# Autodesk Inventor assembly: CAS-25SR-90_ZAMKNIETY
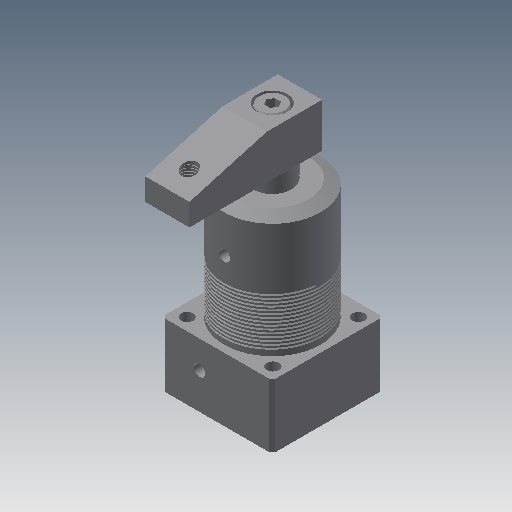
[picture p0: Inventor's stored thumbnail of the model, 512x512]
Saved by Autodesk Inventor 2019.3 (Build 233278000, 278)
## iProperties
Created: 2010-02
Part Number: CAS-25SR-90_ZAMKNIETY
Material: Ogólny
Document SubType Name: Assembly
Designer: CADENGINEERING4
Sending System: PRO/ENGINEER BY PARAMETRIC TECHNOLOGY CORPORATION, 2007170
Preprocessor: PRO/ENGINEER BY PARAMETRIC TECHNOLOGY CORPORATION, 2007170
Title: CAS-25S_ASM
Author: Administrator
Revision Number: 2LAST_VERSION
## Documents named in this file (8)
- D:\Vault_2016\Projekty\STRONA\Pneumatic\Line ; Pipe connecct - type\cas-25s_asm\CAS-25SR-90_ZAMKNIETY.iam
- D:\Vault_2016\Projekty\STRONA\Pneumatic\Line ; Pipe connecct - type\cas-25s_asm\CAS-25BT.ipt
- D:\Vault_2016\Projekty\STRONA\Pneumatic\Line ; Pipe connecct - type\cas-25s_asm\CAS-25SHSG.ipt
- D:\Vault_2016\Projekty\STRONA\Pneumatic\Line ; Pipe connecct - type\cas-25s_asm\CAS-25HG.ipt
- D:\Vault_2016\Projekty\STRONA\Pneumatic\Line ; Pipe connecct - type\cas-25s_asm\PRT0001M3.ipt
- D:\Vault_2016\Projekty\STRONA\Pneumatic\Line ; Pipe connecct - type\cas-25s_asm\CAS-25SYABI.ipt
- D:\Vault_2016\Projekty\STRONA\Pneumatic\Line ; Pipe connecct - type\cas-25s_asm\M6LC.ipt
- D:\Vault_2016\Projekty\STRONA\Pneumatic\Line ; Pipe connecct - type\cas-25s_asm\PRT0001.ipt
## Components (10 placed, 10 different names)
1. CAS-25BT_10 — Zestawiające:5, Kątowe:1, Równoległe:1
2. CAS-25SHSG_11 — Zestawiające:1, Zestawiające:2, Zestawiające:4, Zestawiające:5
3. CAS-25HG_12
4. PRT0001M3_13
5. PRT0001M3_14
6. PRT0001M3_15
7. PRT0001M3_16
8. CAS-25SYABI_17 — Zestawiające:1, Zestawiające:3, Zestawiające:4, Kątowe:1, Równoległe:1
9. M6LC_18 — Zestawiające:2, Zestawiające:3
10. PRT0001_19
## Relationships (7: Mate 5, Angle 1, Flush 1)
- Zestawiające:1 [Mate]: CAS-25SHSG_11 ↔ CAS-25SYABI_17
- Zestawiające:2 [Mate]: CAS-25SHSG_11 ↔ M6LC_18
- Zestawiające:3 [Mate]: CAS-25SYABI_17 ↔ M6LC_18
- Zestawiające:4 [Mate]: CAS-25SHSG_11 ↔ CAS-25SYABI_17
- Zestawiające:5 [Mate]: CAS-25BT_10 ↔ CAS-25SHSG_11
- Kątowe:1 [Angle]: CAS-25BT_10 ↔ CAS-25SYABI_17
- Równoległe:1 [Flush]: CAS-25BT_10 ↔ CAS-25SYABI_17
